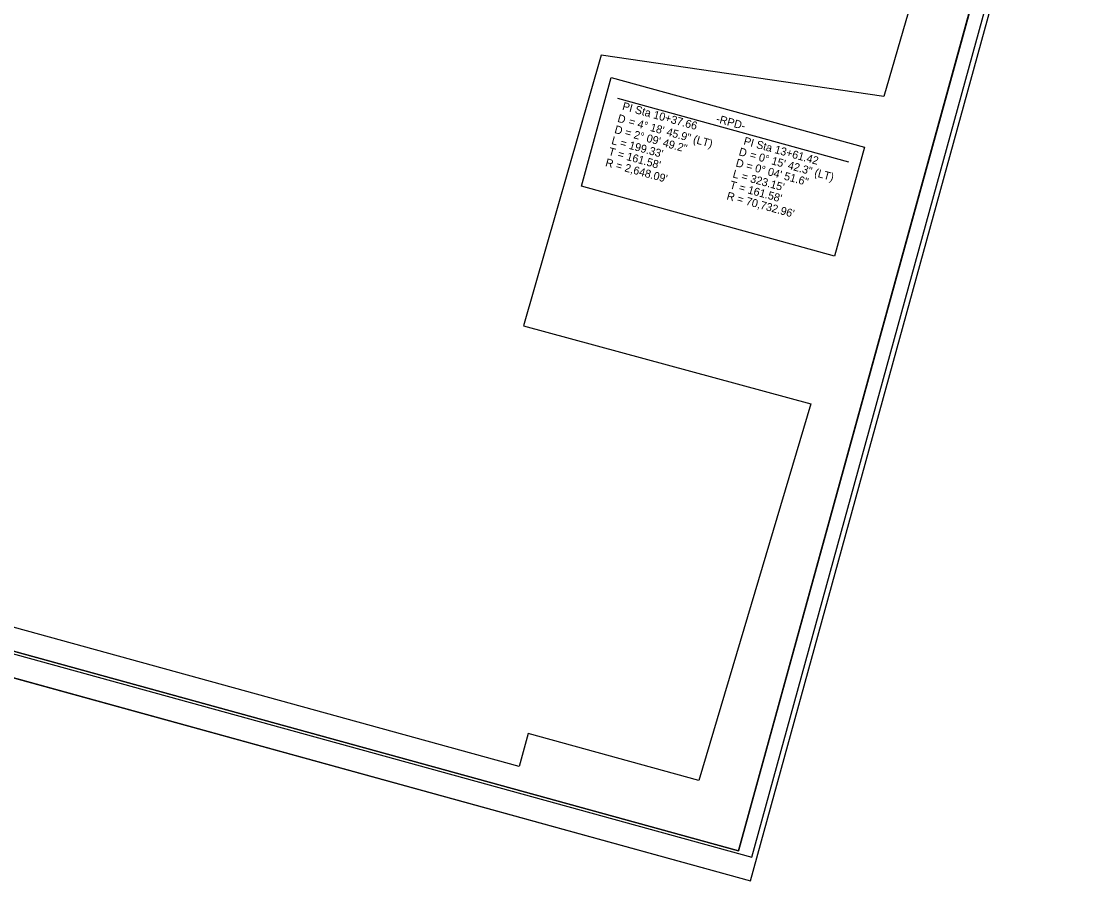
# Model space of a CAD drawing. Extents: x 1641192 to 2864602, y 841295 to 973236.
# Drawn here: x 1642177 to 1643106, y 841295 to 842047 of the extents above; entities that cross this region are included whole.
import ezdxf

# ---------------------------------------------------------------- set-up
doc = ezdxf.new("R2010")
doc.units = 0
for name, color, linetype in [('Prop Horizontal Alignment Curve and Spiral Data', 7, 'Continuous'), ('Sheet Clip Boundary CELL', 7, 'Continuous'), ('Sheet Cutting Line CELL', 7, 'Continuous'), ('Sheet Plan CELL', 7, 'Continuous'), ('Sheet Plot Border Inside CELL', 7, 'Continuous'), ('Sheet Plot Border Outside CELL', 7, 'Continuous')]:
    doc.layers.add(name, color=color, linetype=linetype)

msp = doc.modelspace()

# ---------------------------------------------------------------- linework, layer by layer
at = {"layer": 'Prop Horizontal Alignment Curve and Spiral Data'}
msp.add_line((1642698.89, 841979.32), (1642901, 841923.7), dxfattribs=at)
msp.add_lwpolyline([(1642693.49, 841997.4), (1642914.88, 841936.47), (1642888.7, 841841.33), (1642667.31, 841902.25)], close=True, dxfattribs=at)
at = {"layer": 'Sheet Clip Boundary CELL'}
msp.add_lwpolyline([(1642834.84, 842332.26), (1642796.64, 842193.46), (1642979.12, 842143.25), (1642931.91, 841980.78), (1642684.68, 842016.94), (1642616.55, 841780.17), (1642867.94, 841712.2), (1642769.91, 841383), (1642620.74, 841424.05), (1642612.78, 841395.12), (1641412.11, 841725.54), (1641476.31, 841958.82), (1641627.07, 841958.82), (1641755.49, 842119.21), (1641752.38, 842181.83), (1641796.56, 842667.29)], dxfattribs=at)
at = {"layer": 'Sheet Cutting Line CELL'}
msp.add_line((1641192.11, 841741.99), (1642815.27, 841295.31), dxfattribs=at)
at = {"layer": 'Sheet Plan CELL'}
for points in [[(1643083.47, 842333.88), (1641637.2, 842731.89), (1641358.6, 841719.52), (1642804.85, 841321.52)], [(1641358.6, 841719.52), (1641637.16, 842731.87), (1642890.57, 842386.98), (1642850.76, 842242.29), (1643043.63, 842189.2), (1642804.85, 841321.52)]]:
    msp.add_lwpolyline(points, close=True, dxfattribs=at)
at = {"layer": 'Sheet Plot Border Inside CELL'}
msp.add_lwpolyline([(1641209.95, 841757.82), (1642816.23, 841315.8), (1643096.16, 842332.97), (1641489.87, 842775.01)], close=True, dxfattribs=at)
at = {"layer": 'Sheet Plot Border Outside CELL'}
msp.add_lwpolyline([(1641192.11, 841741.99), (1642815.27, 841295.31), (1643105.8, 842351.06), (1641482.64, 842797.74)], close=True, dxfattribs=at)
msp.add_lwpolyline([(1641192.11, 841741.99), (1642815.27, 841295.31), (1643105.8, 842351.06), (1641482.64, 842797.74)], close=True, dxfattribs=at)

# ---------------------------------------------------------------- texts
at = {"layer": 'Prop Horizontal Alignment Curve and Spiral Data'}
for s, p in [('PI Sta 10+37.66', (1642702.55, 841969.31)), ('D ', (1642698.4, 841958.71)), ('= 4%%d 18\' 45.9" (LT)', (1642708.02, 841955.98)), ('-RPD-', (1642784.6, 841958.32)), ('D = 2%%d 09\' 49.2"', (1642695.73, 841948.99)), ("L = 199.33'", (1642693.08, 841939.35)), ('PI Sta 13+61.42', (1642808.64, 841938.87)), ("T = 161.58'", (1642690.42, 841929.71)), ('D ', (1642804.46, 841929.52)), ('= 0%%d 15\' 42.3" (LT)', (1642814.08, 841926.8)), ("R = 2,648.09'", (1642687.77, 841920.07)), ('D = 0%%d 04\' 51.6"', (1642801.79, 841919.81)), ("L = 323.15'", (1642799.13, 841910.17)), ("T = 161.58'", (1642796.48, 841900.53)), ("R = 70,732.96'", (1642793.83, 841890.88))]:
    msp.add_text(s, height=7, rotation=344.6135, dxfattribs=at).set_placement(p)

doc.saveas('drawing.dxf')
